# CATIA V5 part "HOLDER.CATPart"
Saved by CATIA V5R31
Part number: HOLDER
Revision: 01
Nomenclature: HOLDER
Source: Unknown
Property "部品番号(B社)": "MOLD444444"
Property "部品名称(B社)": "HOLDER"
Property "Version(B社)": "01"
Property "材質(B社)": "PBT G30"
Bounding box of the stored display mesh (mm): x -14.75 to 14.75, y -8 to 8, z -20 to 16
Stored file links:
  \\solize.local\damia\dept\DDE_Design\10_order\2305701_JAMA_変換検証STEP3_お手本モデル作成\work\03_東洋電装_スイッチ\10_CATIA_V5\HOLDER.CATPart
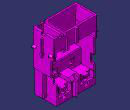
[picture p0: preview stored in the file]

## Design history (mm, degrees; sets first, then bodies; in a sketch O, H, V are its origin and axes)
WSupportSet1: ActiveGrid {3dwsupport RefPoint {point stored without definition}, 3DWOS ({wsupport Support xy-plane, RefPoint {3dwsupport}, GridIn {cartgrid Value 100, Stepbid1 0, Value 100, Stepbid2 0, Direction (1, 0, 0)}, GeometricData ({line type PtDir, Direction (1, 0, 0), Support xy-plane}; {line type PtDir, Direction (0, 1, 0), Support xy-plane})}; {wsupport Support yz-plane, RefPoint {3dwsupport}, GridIn {cartgrid Value 100, Stepbid1 0, Value 100, Stepbid2 0, Direction (0, 1, 0)}, GeometricData ({line type PtDir, Direction (0, 1, 0), Support yz-plane}; {line type PtDir, Direction (0, 0, 1), Support yz-plane})}; {wsupport Support zx-plane, RefPoint {3dwsupport}, GridIn {cartgrid Value 100, Stepbid1 0, Value 100, Stepbid2 0, Direction (0, 0, 1)}, GeometricData ({line type PtDir, Direction (0, 0, 1), Support zx-plane}; {line type PtDir, Direction (1, 0, 0), Support zx-plane})}), GeometricData ({line type PtDir, RefPoint {point stored without definition}, Direction (1, 0, 0), Support xy-plane}; {line type PtDir, RefPoint {point stored without definition}, Direction (0, 1, 0), Support xy-plane}; {line type PtDir, RefPoint {point stored without definition}, Direction (0, 1, 0), Support yz-plane}; {line type PtDir, RefPoint {point stored without definition}, Direction (0, 0, 1), Support yz-plane}; {line type PtDir, RefPoint {point stored without definition}, Direction (0, 0, 1), Support zx-plane}; {line type PtDir, RefPoint {point stored without definition}, Direction (1, 0, 0), Support zx-plane})}
Body1 (main body)
  Solid1: solid without history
